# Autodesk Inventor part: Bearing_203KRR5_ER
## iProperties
Created: 2008-11
Part Number: Bearing_203KRR5_ER
Document SubType Name: Modeling
Designer: ETUDIANT
Author: ETUDIANT
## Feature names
1. Révolution1 [Revolution]
